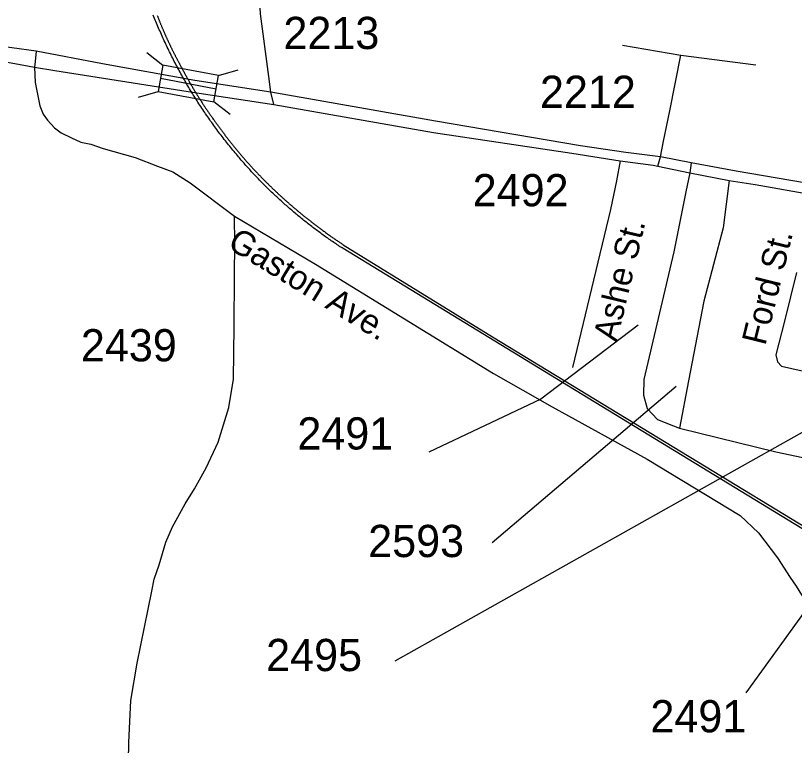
# Model space of a CAD drawing. Extents: x 1364363 to 1407445, y 538563 to 573342.
# Drawn here: x 1373269 to 1376290, y 551955 to 554787 of the extents above; entities that cross this region are included whole.
import ezdxf

# ---------------------------------------------------------------- set-up
doc = ezdxf.new("R2010")
doc.units = 0
for name, color, linetype in [('Exist Railroad Mainline', 7, 'Continuous'), ('Exist Railroad Siding', 7, 'Continuous'), ('Exist Road Primary US Divided Attributed', 7, 'Continuous'), ('Exist Road Primary US Structure Standard Bridge CELL', 7, 'Continuous'), ('Exist Road Secondary Type 51 Attributed', 7, 'Continuous'), ('Exist Road Secondary Type 51 Label', 7, 'Continuous'), ('Exist Road Secondary Type 51 Number Label', 7, 'Continuous')]:
    doc.layers.add(name, color=color, linetype=linetype)

msp = doc.modelspace()

# ---------------------------------------------------------------- linework, layer by layer
at = {"layer": 'Exist Railroad Mainline'}
for points in [[(1374129.8, 554243.5), (1374125.4, 554248.7), (1374121, 554253.9), (1374116.8, 554259.1), (1374112.3, 554264.3), (1374108, 554269.6), (1374103.7, 554274.9), (1374099.5, 554280.1), (1374095.2, 554285.5), (1374091, 554290.7), (1374086.7, 554296.1), (1374082.6, 554301.4), (1374078.4, 554306.7), (1374074.2, 554312.1), (1374070.1, 554317.5), (1374066, 554322.9), (1374061.9, 554328.3), (1374057.7, 554333.7), (1374053.7, 554339.1), (1374049.6, 554344.6), (1374045.6, 554350.1), (1374041.6, 554355.5), (1374037.6, 554361.1), (1374033.6, 554366.6), (1374029.7, 554372), (1374025.7, 554377.6), (1374021.9, 554383.1), (1374018, 554388.7), (1374014.1, 554394.3), (1374010.2, 554399.9), (1374006.3, 554405.5), (1374002.6, 554411.1), (1373998.7, 554416.7), (1373995, 554422.4), (1373991.3, 554428), (1373987.5, 554433.7), (1373983.8, 554439.4), (1373980.1, 554445), (1373976.4, 554450.7), (1373972.7, 554456.5), (1373969.1, 554462.2), (1373965.5, 554468), (1373961.8, 554473.7), (1373958.3, 554479.5), (1373954.8, 554485.2), (1373951.3, 554491.1), (1373947.6, 554496.9), (1373944.1, 554502.7), (1373940.7, 554508.5), (1373937.2, 554514.4), (1373933.7, 554520.2), (1373930.4, 554526), (1373927, 554531.9), (1373923.6, 554537.9), (1373920.2, 554543.7), (1373916.8, 554549.7), (1373913.7, 554555.6), (1373910.3, 554561.6), (1373907, 554567.5), (1373903.7, 554573.5), (1373900.5, 554579.5), (1373897.4, 554585.4), (1373894.2, 554591.4), (1373891, 554597.4), (1373887.7, 554603.4), (1373884.6, 554609.4), (1373881.7, 554615.5), (1373878.5, 554621.5), (1373875.4, 554627.5), (1373872.3, 554633.6), (1373869.4, 554639.7), (1373866.4, 554645.8), (1373863.4, 554651.9), (1373860.3, 554658), (1373857.5, 554664.2), (1373854.5, 554670.3), (1373851.6, 554676.4), (1373848.8, 554682.5), (1373845.9, 554688.7), (1373843.1, 554695), (1373840.2, 554701.1), (1373837.5, 554707.3), (1373834.7, 554713.5), (1373832, 554719.7), (1373829.3, 554725.9), (1373826.5, 554732.1), (1373823.8, 554738.4), (1373821.3, 554744.6), (1373818.6, 554750.9), (1373816, 554757.2), (1373813.4, 554763.4), (1373810.7, 554769.7), (1373808.3, 554776), (1373805.8, 554782.3), (1373803.2, 554788.6)], [(1374539.8, 553882.6), (1374535.2, 553885.6), (1374530.4, 553888.6), (1374525.8, 553891.6), (1374521.2, 553894.7), (1374516.6, 553897.8), (1374512, 553900.8), (1374507.5, 553903.9), (1374502.9, 553907), (1374498.3, 553910.1), (1374493.7, 553913.2), (1374489.1, 553916.4), (1374484.6, 553919.5), (1374480.1, 553922.7), (1374475.5, 553926), (1374471, 553929.1), (1374466.5, 553932.4), (1374462, 553935.5), (1374457.5, 553938.8), (1374453, 553942.1), (1374448.6, 553945.4), (1374444.1, 553948.6), (1374439.6, 553951.9), (1374435.2, 553955.2), (1374430.8, 553958.6), (1374426.4, 553961.9), (1374422, 553965.3), (1374417.7, 553968.6), (1374413.2, 553972), (1374408.8, 553975.4), (1374404.5, 553978.8), (1374400.1, 553982.2), (1374395.7, 553985.6), (1374391.4, 553989.1), (1374387, 553992.5), (1374382.7, 553996), (1374378.4, 553999.5), (1374374.1, 554003), (1374369.9, 554006.5), (1374365.6, 554010), (1374361.3, 554013.6), (1374357, 554017), (1374352.9, 554020.6), (1374348.7, 554024.2), (1374344.4, 554027.8), (1374340.2, 554031.4), (1374336, 554035), (1374331.8, 554038.6), (1374327.7, 554042.3), (1374323.3, 554045.9), (1374319.2, 554049.6), (1374315.1, 554053.2), (1374311, 554056.9), (1374306.8, 554060.6), (1374302.7, 554064.3), (1374298.6, 554068.1), (1374294.5, 554071.7), (1374290.5, 554075.5), (1374286.3, 554079.3), (1374282.3, 554083.1), (1374278.2, 554086.8), (1374274.2, 554090.6), (1374270.2, 554094.5), (1374266.2, 554098.3), (1374262.2, 554102), (1374258.2, 554105.9), (1374254.2, 554109.8), (1374250.2, 554113.6), (1374246.3, 554117.6), (1374242.4, 554121.4), (1374238.5, 554125.3), (1374234.5, 554129.3), (1374230.7, 554133.2), (1374226.8, 554137.1), (1374222.9, 554141.1), (1374219, 554145), (1374215.1, 554149), (1374211.3, 554153), (1374207.5, 554157), (1374203.6, 554161), (1374199.9, 554165), (1374196, 554169), (1374192.2, 554173), (1374188.5, 554177.1), (1374184.7, 554181.2), (1374181, 554185.2), (1374177.2, 554189.4), (1374173.5, 554193.4), (1374169.8, 554197.5), (1374166.2, 554201.7), (1374162.4, 554205.8), (1374158.8, 554210), (1374155.1, 554214.1), (1374151.4, 554218.3), (1374147.7, 554222.5), (1374144.1, 554226.6), (1374140.5, 554230.8), (1374137, 554235.1), (1374133.4, 554239.3), (1374129.8, 554243.5)], [(1377375.6, 552151.4), (1375413.5, 553349.2), (1374539.8, 553882.6)]]:
    msp.add_lwpolyline(points, dxfattribs=at)
at = {"layer": 'Exist Railroad Siding'}
for points in [[(1373818.6, 554787.2), (1373819.3, 554784.9), (1373820.3, 554782.8), (1373821.2, 554780.5), (1373822, 554778.3), (1373822.9, 554776.1), (1373823.7, 554773.9), (1373824.7, 554771.6), (1373825.5, 554769.4), (1373826.4, 554767.2), (1373827.2, 554765), (1373828.1, 554762.8), (1373829, 554760.6), (1373829.9, 554758.4), (1373830.9, 554756.2), (1373831.7, 554754), (1373832.7, 554751.8), (1373833.5, 554749.5), (1373834.5, 554747.3), (1373835.4, 554745.1), (1373836.2, 554742.9), (1373837.3, 554740.7), (1373838.1, 554738.6), (1373839.1, 554736.4), (1373840, 554734.2), (1373840.9, 554731.9), (1373841.9, 554729.8), (1373842.9, 554727.6), (1373843.7, 554725.4), (1373844.8, 554723.2), (1373845.6, 554721), (1373846.6, 554718.9), (1373847.6, 554716.7), (1373848.5, 554714.5), (1373849.5, 554712.3), (1373850.5, 554710.1), (1373851.5, 554707.9), (1373852.3, 554705.8), (1373853.4, 554703.6), (1373854.4, 554701.5), (1373855.4, 554699.3), (1373856.3, 554697.1), (1373857.4, 554695), (1373858.4, 554692.7), (1373859.4, 554690.6), (1373860.3, 554688.4), (1373861.4, 554686.2), (1373862.4, 554684.1), (1373863.4, 554681.9), (1373864.3, 554679.8), (1373865.4, 554677.6), (1373866.4, 554675.5), (1373867.5, 554673.3), (1373868.5, 554671.2), (1373869.5, 554669.1), (1373870.5, 554666.9), (1373871.6, 554664.8), (1373872.6, 554662.6), (1373873.8, 554660.5), (1373874.8, 554658.3), (1373875.7, 554656.2), (1373876.8, 554654), (1373877.9, 554651.9), (1373879, 554649.8), (1373880, 554647.6), (1373881.2, 554645.5), (1373882.1, 554643.4), (1373883.2, 554641.2), (1373884.3, 554639.1), (1373885.4, 554637), (1373886.5, 554634.9), (1373887.6, 554632.8), (1373888.6, 554630.7), (1373889.8, 554628.6), (1373890.9, 554626.4), (1373892, 554624.3), (1373893.1, 554622.2), (1373894.2, 554620.1), (1373895.3, 554618), (1373896.3, 554615.9), (1373897.5, 554613.8), (1373898.6, 554611.7), (1373899.7, 554609.5), (1373900.8, 554607.4), (1373902, 554605.4), (1373903.1, 554603.2)], [(1373903.1, 554603.2), (1373904.6, 554600.4), (1373906.2, 554597.6), (1373907.5, 554594.8), (1373909, 554591.9), (1373910.5, 554589.1), (1373912, 554586.3), (1373913.5, 554583.5), (1373915, 554580.7), (1373916.5, 554577.9), (1373918, 554575), (1373919.5, 554572.2), (1373921, 554569.5), (1373922.5, 554566.7), (1373924, 554563.9), (1373925.5, 554561.1), (1373927, 554558.3), (1373928.6, 554555.5), (1373930.2, 554552.7), (1373931.6, 554549.9), (1373933.2, 554547.2), (1373934.8, 554544.4), (1373936.4, 554541.6), (1373937.8, 554538.8), (1373939.5, 554536.1), (1373941, 554533.3), (1373942.7, 554530.6), (1373944.2, 554527.7), (1373945.7, 554525), (1373947.4, 554522.2), (1373949, 554519.5), (1373950.7, 554516.8), (1373952.2, 554514), (1373953.8, 554511.2), (1373955.4, 554508.6), (1373957, 554505.8), (1373958.7, 554503.1), (1373960.4, 554500.3), (1373962, 554497.6), (1373963.6, 554494.9), (1373965.2, 554492.2), (1373966.9, 554489.4), (1373968.6, 554486.8), (1373970.2, 554484), (1373971.9, 554481.3), (1373973.6, 554478.6), (1373975.3, 554475.9), (1373976.9, 554473.2), (1373978.7, 554470.5), (1373980.3, 554467.8), (1373982, 554465.1), (1373983.8, 554462.4), (1373985.4, 554459.8), (1373987.2, 554457), (1373988.9, 554454.4), (1373990.5, 554451.7), (1373992.3, 554449), (1373994, 554446.3), (1373995.8, 554443.7), (1373997.5, 554441), (1373999.3, 554438.3), (1374001, 554435.7), (1374002.7, 554433), (1374004.5, 554430.4), (1374006.2, 554427.8), (1374008, 554425.1), (1374009.7, 554422.4), (1374011.7, 554419.8), (1374013.4, 554417.2), (1374015.2, 554414.5), (1374017, 554411.9), (1374018.7, 554409.3), (1374020.5, 554406.6), (1374022.3, 554404), (1374024.2, 554401.4), (1374026, 554398.8), (1374027.8, 554396.2), (1374029.6, 554393.6), (1374031.5, 554391), (1374033.3, 554388.4), (1374035.1, 554385.7), (1374037, 554383.2), (1374038.8, 554380.6), (1374040.6, 554378), (1374042.5, 554375.4), (1374044.4, 554372.8), (1374046.2, 554370.3), (1374048.2, 554367.7), (1374050, 554365.1), (1374051.9, 554362.6), (1374053.7, 554360), (1374055.7, 554357.4), (1374057.5, 554354.9), (1374059.5, 554352.3), (1374061.4, 554349.7), (1374063.2, 554347.2), (1374065.1, 554344.7), (1374067.1, 554342.1), (1374069, 554339.5), (1374071, 554337.1)], [(1374071, 554337.1), (1374073, 554334.4), (1374075, 554331.7), (1374077, 554329), (1374079, 554326.3), (1374081, 554323.6), (1374083, 554321), (1374085.1, 554318.3), (1374087.1, 554315.7), (1374089.1, 554313), (1374091.2, 554310.4), (1374093.3, 554307.7), (1374095.3, 554305), (1374097.4, 554302.4), (1374099.5, 554299.8), (1374101.5, 554297.2), (1374103.6, 554294.5), (1374105.8, 554291.9), (1374107.7, 554289.3), (1374109.9, 554286.6), (1374112, 554284.1), (1374114.1, 554281.4), (1374116.2, 554278.8), (1374118.4, 554276.2), (1374120.3, 554273.6), (1374122.5, 554271.1), (1374124.7, 554268.4), (1374126.9, 554265.9), (1374129, 554263.3), (1374131.1, 554260.7), (1374133.3, 554258.1), (1374135.4, 554255.6), (1374137.5, 554253), (1374139.7, 554250.4), (1374141.9, 554247.9), (1374144.1, 554245.3), (1374146.3, 554242.8), (1374148.3, 554240.2), (1374150.6, 554237.7), (1374152.7, 554235.2), (1374155, 554232.6), (1374157.3, 554230.1), (1374159.4, 554227.6), (1374161.7, 554225.1), (1374163.9, 554222.6), (1374166.2, 554220.1), (1374168.2, 554217.5), (1374170.5, 554215), (1374172.7, 554212.5), (1374175, 554210.1), (1374177.2, 554207.5), (1374179.5, 554205.1), (1374181.8, 554202.6), (1374184, 554200.1), (1374186.3, 554197.6), (1374188.5, 554195.2), (1374190.8, 554192.7), (1374193.1, 554190.3), (1374195.4, 554187.8), (1374197.6, 554185.3), (1374200, 554182.9), (1374202.3, 554180.4), (1374204.5, 554178), (1374206.9, 554175.6), (1374209.1, 554173.1), (1374211.5, 554170.7), (1374213.7, 554168.3), (1374216.1, 554165.9), (1374218.5, 554163.5), (1374220.7, 554161), (1374223.1, 554158.7), (1374225.5, 554156.2), (1374227.8, 554153.9), (1374230.2, 554151.5), (1374232.5, 554149.1), (1374234.9, 554146.7), (1374237.2, 554144.4), (1374239.6, 554142), (1374242, 554139.6), (1374244.4, 554137.3), (1374246.8, 554134.9), (1374249.1, 554132.5), (1374251.5, 554130.2), (1374253.8, 554127.9), (1374256.4, 554125.5), (1374258.8, 554123.2), (1374261.1, 554120.8), (1374263.5, 554118.5), (1374266, 554116.2), (1374268.4, 554113.9), (1374270.9, 554111.6), (1374273.2, 554109.3), (1374275.8, 554106.9), (1374278.1, 554104.7), (1374280.6, 554102.4), (1374283, 554100), (1374285.5, 554097.8), (1374288, 554095.5), (1374290.3, 554093.2), (1374292.9, 554091)], [(1374292.9, 554091), (1374295.3, 554088.8), (1374297.5, 554086.7), (1374299.9, 554084.6), (1374302.2, 554082.5), (1374304.6, 554080.3), (1374306.8, 554078.2), (1374309.3, 554076.1), (1374311.7, 554074), (1374314, 554071.8), (1374316.4, 554069.7), (1374318.7, 554067.7), (1374321.1, 554065.5), (1374323.4, 554063.5), (1374325.9, 554061.4), (1374328.3, 554059.3), (1374330.6, 554057.2), (1374333, 554055.1), (1374335.3, 554053.1), (1374337.7, 554051), (1374340.3, 554048.9), (1374342.6, 554046.9), (1374345, 554044.8), (1374347.3, 554042.7), (1374349.8, 554040.7), (1374352.3, 554038.7), (1374354.6, 554036.6), (1374357, 554034.6), (1374359.5, 554032.6), (1374361.9, 554030.5), (1374364.4, 554028.5), (1374366.7, 554026.4), (1374369.3, 554024.4), (1374371.6, 554022.4), (1374374.1, 554020.4), (1374376.5, 554018.4), (1374379, 554016.4), (1374381.4, 554014.4), (1374383.8, 554012.4), (1374386.4, 554010.4), (1374388.8, 554008.4), (1374391.2, 554006.4), (1374393.8, 554004.4), (1374396.2, 554002.5), (1374398.7, 554000.5), (1374401.2, 553998.5), (1374403.6, 553996.5), (1374406.1, 553994.6), (1374408.6, 553992.6), (1374411.1, 553990.7), (1374413.7, 553988.8), (1374416.1, 553986.8), (1374418.6, 553984.9), (1374421.2, 553983), (1374423.6, 553981), (1374426.1, 553979.1), (1374428.6, 553977.1), (1374431.1, 553975.2), (1374433.7, 553973.3), (1374436.1, 553971.4), (1374438.8, 553969.4), (1374441.3, 553967.6), (1374443.7, 553965.6), (1374446.3, 553963.7), (1374448.8, 553961.9), (1374451.4, 553960), (1374453.9, 553958), (1374456.5, 553956.2), (1374459, 553954.3), (1374461.4, 553952.5), (1374464.1, 553950.6), (1374466.6, 553948.7), (1374469.2, 553946.9), (1374471.7, 553945), (1374474.4, 553943.1), (1374476.8, 553941.3), (1374479.5, 553939.4), (1374482, 553937.6), (1374484.6, 553935.7), (1374487.3, 553934), (1374489.7, 553932.1), (1374492.4, 553930.3), (1374495, 553928.4), (1374497.5, 553926.6), (1374500.1, 553924.8), (1374502.8, 553923), (1374505.3, 553921.2), (1374508, 553919.4), (1374510.5, 553917.7), (1374513.1, 553915.8), (1374515.8, 553914.1), (1374518.4, 553912.3), (1374521, 553910.5), (1374523.6, 553908.7), (1374526.2, 553906.9), (1374528.9, 553905.2), (1374531.5, 553903.4), (1374534.1, 553901.6), (1374536.7, 553899.9), (1374539.4, 553898.1)], [(1374539.4, 553898.1), (1375118.3, 553540.2), (1375881.2, 553076.7), (1377437.4, 552130)]]:
    msp.add_lwpolyline(points, dxfattribs=at)
at = {"layer": 'Exist Road Primary US Divided Attributed'}
for points in [[(1373348.3, 554648.3), (1373253.9, 554661.6), (1372858.1, 554722.9), (1372636.8, 554760.2), (1372310.4, 554822.4), (1372073.5, 554861.4), (1371761, 554918.3), (1371523.5, 554940.2), (1371351.9, 554980.8)], [(1372009.4, 554827.6), (1373265.5, 554600.8), (1373342.2, 554586.8)], [(1373964.8, 554534.5), (1373606.6, 554600.3), (1373348.3, 554648.3)], [(1373342.2, 554586.8), (1373421.9, 554573.7), (1373937.9, 554492.4)], [(1374259.2, 554489.2), (1373964.8, 554534.5)], [(1373937.9, 554492.4), (1373981.5, 554485.6), (1374270.9, 554441.7)], [(1375769.8, 554238.8), (1375635.8, 554255.8), (1375459.7, 554281.5), (1374897.9, 554377.1), (1374259.2, 554489.2)], [(1374270.9, 554441.7), (1374890.2, 554332.7), (1375425.9, 554252.9), (1375614.1, 554223.1)], [(1375889.4, 554215.8), (1375769.8, 554238.8)], [(1375614.1, 554223.1), (1375742.6, 554206.2), (1375759.8, 554202.6)], [(1377259.9, 553983.6), (1376648.6, 554082.9), (1376540.9, 554101.7), (1376063.9, 554182.9), (1375889.4, 554215.8)], [(1375759.8, 554202.6), (1375884.1, 554176.7)], [(1375884.1, 554176.7), (1376037.3, 554147.2)], [(1376037.3, 554147.2), (1376137.2, 554132.1), (1376371.8, 554090.8)]]:
    msp.add_lwpolyline(points, dxfattribs=at)
at = {"layer": 'Exist Road Primary US Structure Standard Bridge CELL'}
for p, q in [((1373777.6, 554643.2), (1373840.7, 554594.8)), ((1374056.6, 554553.9), (1374132.9, 554576.1)), ((1373831.1, 554543.8), (1374047, 554503.2)), ((1373745.2, 554470.6), (1373821.5, 554492.8)), ((1374037.6, 554453.2), (1374100.7, 554404.7))]:
    msp.add_line(p, q, dxfattribs=at)
msp.add_lwpolyline([(1373821.5, 554492.8), (1374037.4, 554452.2), (1374056.6, 554554.2), (1373840.7, 554594.8)], close=True, dxfattribs=at)
at = {"layer": 'Exist Road Secondary Type 51 Attributed'}
for p, q in [((1375622.6, 554672.6), (1375849.2, 554633.2)), ((1375849.2, 554633.2), (1376140.5, 554595.9))]:
    msp.add_line(p, q, dxfattribs=at)
for points in [[(1374259.2, 554489.2), (1374251.6, 554550.6), (1374219.1, 554794.1), (1374209, 554993.4), (1374174.8, 555172.2), (1374122.3, 555351.5), (1374043.2, 555585.2), (1373941, 555863.4), (1373861.7, 556089.1), (1373833.5, 556191.4), (1373768.6, 556362.5), (1373722.7, 556466.2), (1373683.1, 556546.7)], [(1373348.3, 554648.3), (1373344.6, 554609.2), (1373342.2, 554586.8)], [(1375769.8, 554238.8), (1375781.8, 554299.7), (1375806, 554418), (1375849.2, 554633.2)], [(1373342.2, 554586.8), (1373345, 554527.4), (1373363.2, 554436.2), (1373376.4, 554404.7), (1373393, 554381.5), (1373419.5, 554351.7), (1373446, 554331.8), (1373485.7, 554312), (1373522.2, 554295.4), (1373560.4, 554287.7), (1373609.1, 554271.4), (1373732.4, 554235.7), (1373820, 554203.2), (1373878.4, 554180.5), (1373946.5, 554138.3), (1374117.7, 554009.2)], [(1374270.9, 554441.7), (1374259.2, 554489.2)], [(1375759.8, 554202.6), (1375769.8, 554238.8)], [(1375614.1, 554223.1), (1375599.9, 554146.4), (1375576.5, 554034.7), (1375429.5, 553421.8)], [(1375889.4, 554215.8), (1375884.1, 554176.7)], [(1375884.1, 554176.7), (1375868.1, 554103.3), (1375822.3, 553869.8), (1375706.1, 553375.4), (1375704.4, 553314.1), (1375719.3, 553262.7), (1375759.1, 553219.6), (1375820.6, 553195.1), (1375844.1, 553185.7)], [(1376037.3, 554147.2), (1376013.5, 553963.1), (1375938.9, 553678.5), (1375878.4, 553369.5), (1375844.1, 553185.7)], [(1373710.7, 551724.2), (1373705.3, 551824.4), (1373708.1, 551966.4), (1373716, 552129), (1373740, 552274.4), (1373797.9, 552554.3), (1373807, 552600.5), (1373826.5, 552655.7), (1373852.4, 552743.4), (1373877.3, 552803.2), (1373927.1, 552892.7), (1373962.8, 552951.2), (1374008.2, 553032.3), (1374055.2, 553132.2), (1374096.5, 553266.1), (1374113.7, 553375.7), (1374116.9, 553580.2), (1374117.6, 553776.7), (1374119.2, 553903.1), (1374117.7, 554009.2)], [(1374117.7, 554009.2), (1374432.9, 553822.1), (1375122.9, 553398.4), (1375350, 553268.5), (1375719.3, 553065.2), (1376079.5, 552847.5), (1376150.3, 552780.5), (1376223.8, 552683.4), (1376273.6, 552607.2), (1376297.2, 552573.1), (1376334, 552512.7), (1376404.8, 552405.1), (1376449.4, 552339.5), (1376549.7, 552171.6), (1376615.6, 552074.7), (1376667.6, 552004.8), (1376705.6, 551962.2), (1376837.6, 551878.6)], [(1376297.8, 553789.8), (1376251.5, 553601.3), (1376217.2, 553470.2), (1376224.4, 553443.3), (1376239.6, 553426.6), (1376468.1, 553375.1)], [(1375844.1, 553185.7), (1376218.1, 553094.9), (1376371.4, 553062.5)]]:
    msp.add_lwpolyline(points, dxfattribs=at)
at = {"layer": 'Exist Road Secondary Type 51 Number Label'}
for p, q in [((1375830.7, 553347.7), (1375117.5, 552741.1)), ((1376388.1, 553208.3), (1374740.5, 552282)), ((1376650.5, 552921.4), (1376101.2, 552159))]:
    msp.add_line(p, q, dxfattribs=at)
msp.add_lwpolyline([(1375683.2, 553585.4), (1375306.1, 553298.5), (1374871.6, 553093.5)], dxfattribs=at)

# ---------------------------------------------------------------- texts
at = {"layer": 'Exist Road Secondary Type 51 Label'}
for s, rotation, p in [('Ashe St.', 76.5165, (1375600.8, 553517.7)), ('Gaston Ave.', 328.4429, (1374086.2, 553888.3)), ('Ford St.', 76.1857, (1376176.8, 553503.8))]:
    msp.add_text(s, height=95, rotation=rotation, dxfattribs=at).set_placement(p)
at = {"layer": 'Exist Road Secondary Type 51 Number Label'}
for s, p in [('2213', (1374307.9, 554657.1)), ('2212', (1375302.9, 554428.9)), ('2492', (1375042, 554047)), ('2439', (1373522.4, 553445.3)), ('2491', (1374362, 553103.3)), ('2593', (1374636.7, 552685.9)), ('2495', (1374240.9, 552243.5)), ('2491', (1375731.3, 552005.9))]:
    msp.add_text(s, height=125, dxfattribs=at).set_placement(p)

doc.saveas('drawing.dxf')
